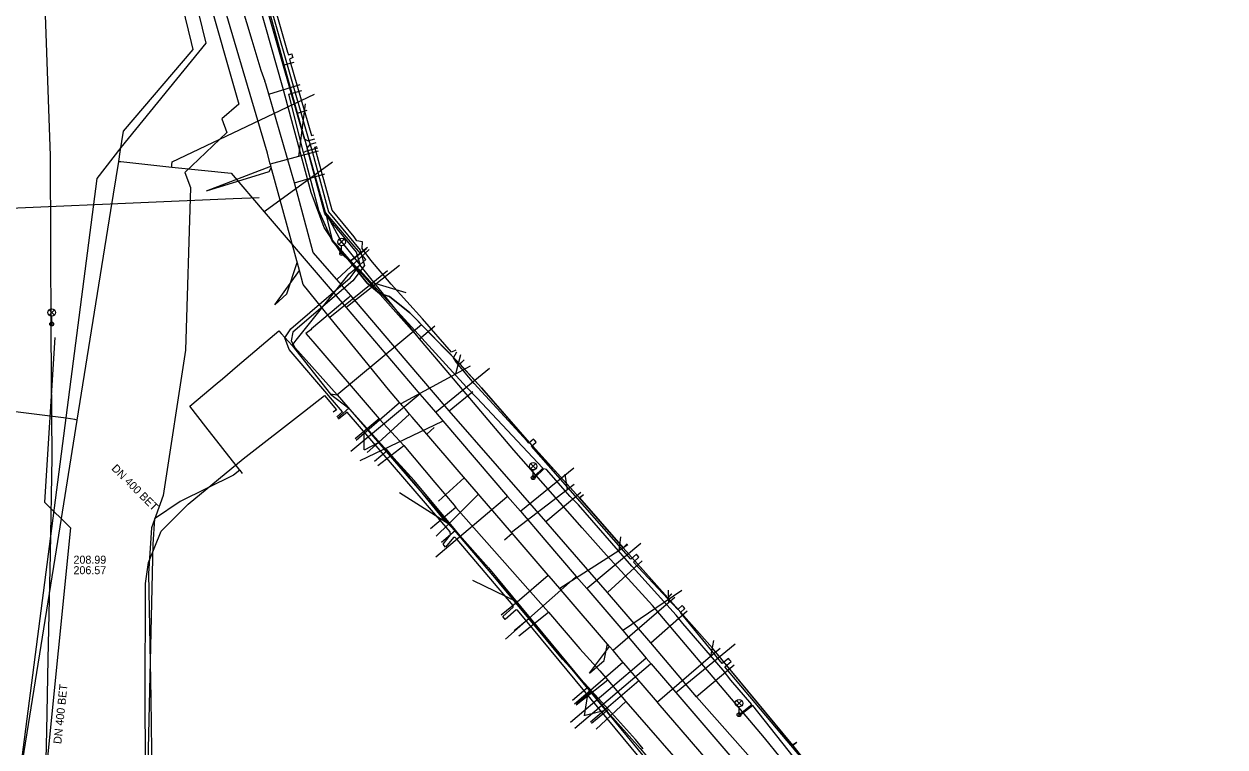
# Model space of a CAD drawing. Extents: x -596228 to -595156, y -1161235 to -1159373.
# Drawn here: x -595381.6 to -595261.6, y -1160803.8 to -1160731.5 of the extents above; entities that cross this region are included whole.
import ezdxf

# ---------------------------------------------------------------- set-up
doc = ezdxf.new("R2010")
doc.units = 0
for name, color, linetype in [('Vrstva 1', 7, 'Continuous'), ('Vrstva 12', 7, 'Continuous'), ('Vrstva 14', 7, 'Continuous'), ('Vrstva 16', 7, 'Continuous'), ('Vrstva 19', 7, 'Continuous'), ('Vrstva 33', 7, 'Continuous'), ('Vrstva 4', 7, 'Continuous'), ('Vrstva 42', 7, 'Continuous'), ('Vrstva 55', 7, 'Continuous'), ('Vrstva 58', 7, 'Continuous'), ('Vrstva 9', 7, 'Continuous')]:
    doc.layers.add(name, color=color, linetype=linetype)

msp = doc.modelspace()

# ---------------------------------------------------------------- linework, layer by layer
at = {"layer": 'Vrstva 1'}
for p, q in [((-595353.54, -1160739.478), (-595354.196, -1160744.737)), ((-595363.38, -1160748.17), (-595356.952, -1160745.709)), ((-595356.55, -1160759.55), (-595354.099, -1160756.146)), ((-595343.414, -1160758.352), (-595346.772, -1160757.366)), ((-595378.54, -1160762.82), (-595379.58, -1160779.28)), ((-595338.006, -1160764.578), (-595338.509, -1160766.51)), ((-595340.631, -1160771.837), (-595341.374, -1160772.48)), ((-595347.635, -1160774.049), (-595347.643, -1160772.399)), ((-595347.59, -1160774.05), (-595346.195, -1160773.314)), ((-595340.184, -1160779.176), (-595337.634, -1160776.852)), ((-595327.564, -1160776.487), (-595327.344, -1160778.072)), ((-595379.58, -1160779.28), (-595376.97, -1160781.85)), ((-595344.09, -1160778.322), (-595339.178, -1160781.454)), ((-595376.97, -1160781.85), (-595379.56, -1160807.66)), ((-595333.602, -1160783.048), (-595332.844, -1160782.396)), ((-595321.998, -1160782.743), (-595322.188, -1160784.155)), ((-595336.8, -1160787.086), (-595332.345, -1160789.262)), ((-595317.258, -1160788.075), (-595317.214, -1160789.37)), ((-595325.1, -1160796.38), (-595323.107, -1160793.714)), ((-595312.705, -1160793.132), (-595313, -1160794.729)), ((-595325.604, -1160800.653), (-595325.25, -1160798.276)), ((-595325.527, -1160800.591), (-595323.666, -1160800.118))]:
    msp.add_line(p, q, dxfattribs=at)
for points in [[(-595363.383, -1160748.172), (-595357.116, -1160746.23), (-595356.909, -1160745.863)], [(-595356.546, -1160759.549), (-595355.349, -1160758.459), (-595354.326, -1160755.316)], [(-595325.103, -1160796.376), (-595323.652, -1160795.129), (-595323.323, -1160793.464)]]:
    msp.add_lwpolyline(points, dxfattribs=at)
at = {"layer": 'Vrstva 12'}
for p, q in [((-595355.61, -1160735.58), (-595357.25, -1160729.61)), ((-595355.61, -1160735.58), (-595354.64, -1160735.32)), ((-595354.28, -1160740.39), (-595355.61, -1160735.58)), ((-595354.28, -1160740.39), (-595353.32, -1160740.12)), ((-595351.5, -1160750.34), (-595354.28, -1160740.39)), ((-595351.5, -1160750.34), (-595349.93, -1160753.24)), ((-595351.5, -1160750.34), (-595350.84, -1160753.1)), ((-595350.84, -1160753.1), (-595348.4, -1160755.86)), ((-595349.93, -1160753.24), (-595348.06, -1160755.57)), ((-595347.3, -1160753.84), (-595349.05, -1160755.22)), ((-595348.4, -1160755.86), (-595348.06, -1160755.57)), ((-595348.4, -1160755.86), (-595342.09, -1160762.98)), ((-595342.09, -1160762.98), (-595348.06, -1160755.57)), ((-595342.21, -1160761.24), (-595341.9, -1160761.56)), ((-595355.94, -1160762.42), (-595354.84, -1160763.62)), ((-595342.09, -1160762.98), (-595340.58, -1160761.66)), ((-595341.9, -1160761.56), (-595338.07, -1160765.48)), ((-595354.84, -1160763.62), (-595350.98, -1160768.5)), ((-595337.62, -1160765.05), (-595338.07, -1160765.48)), ((-595361.8, -1160766.95), (-595360.28, -1160765.65)), ((-595362.33, -1160767.41), (-595361.8, -1160766.95)), ((-595350.98, -1160768.5), (-595349.15, -1160769.91)), ((-595349.15, -1160769.91), (-595350.29, -1160770.89)), ((-595345.33, -1160774.15), (-595349.15, -1160769.91)), ((-595360.07, -1160776.1), (-595363.45, -1160771.76)), ((-595345.33, -1160774.15), (-595346.6, -1160775.22)), ((-595360.07, -1160776.1), (-595359.82, -1160776.41)), ((-595327.7, -1160777.09), (-595326.11, -1160778.86)), ((-595325.71, -1160778.57), (-595326.11, -1160778.86)), ((-595326.11, -1160778.86), (-595321.74, -1160783.87)), ((-595339.91, -1160783.28), (-595338.51, -1160782.1)), ((-595331.18, -1160790.91), (-595338.51, -1160782.1)), ((-595321.35, -1160783.45), (-595321.74, -1160783.87)), ((-595321.74, -1160783.87), (-595319.74, -1160786.1)), ((-595332.62, -1160792.13), (-595331.18, -1160790.91)), ((-595325.23, -1160797.8), (-595326.82, -1160799.11)), ((-595323.21, -1160800.02), (-595325.23, -1160797.8)), ((-595323.21, -1160800.02), (-595324.91, -1160801.41)), ((-595320.5, -1160803.01), (-595323.21, -1160800.02)), ((-595319.73, -1160803.94), (-595320.5, -1160803.01)), ((-595306.05, -1160804.79), (-595307.62, -1160802.85)), ((-595304.41, -1160803.31), (-595304.8, -1160803.59)), ((-595304.8, -1160803.59), (-595302.74, -1160806.18))]:
    msp.add_line(p, q, dxfattribs=at)
for points in [[(-595353.68, -1160744.35), (-595355.17, -1160738.52), (-595353.86, -1160738.15)], [(-595353.68, -1160744.35), (-595353.46, -1160744.19), (-595352.27, -1160743.86)], [(-595349.05, -1160755.22), (-595350.82, -1160753.15), (-595352.17, -1160750.14), (-595353.68, -1160744.35)], [(-595348.06, -1160755.57), (-595347.45, -1160755.04), (-595348.62, -1160753.69), (-595351.5, -1160750.34)], [(-595349.05, -1160755.22), (-595347.34, -1160757.39), (-595346.11, -1160758.42), (-595345.11, -1160758.74), (-595343.08, -1160760.36), (-595342.21, -1160761.24)], [(-595354.84, -1160763.62), (-595354.43, -1160763.11), (-595349.12, -1160756.48), (-595348.4, -1160755.86)], [(-595360.28, -1160765.65), (-595356.17, -1160762.15), (-595355.94, -1160762.42)], [(-595341.9, -1160761.56), (-595350.35, -1160768.6), (-595350.98, -1160768.5)], [(-595325.83, -1160781.85), (-595332.67, -1160774.09), (-595337.43, -1160768.47), (-595339.44, -1160766.1), (-595342.09, -1160762.98)], [(-595338.07, -1160765.48), (-595335.91, -1160767.87), (-595331.12, -1160773.34), (-595327.7, -1160777.09)], [(-595363.45, -1160771.76), (-595365.05, -1160769.71), (-595362.33, -1160767.41)], [(-595338.51, -1160782.1), (-595342.64, -1160777.12), (-595345.33, -1160774.15)], [(-595360.07, -1160776.1), (-595360.7, -1160776.59), (-595366.01, -1160779.21), (-595368.58, -1160780.95), (-595368.76, -1160783.5), (-595369.34, -1160809.83), (-595368.87, -1160823.11), (-595369.36, -1160828.18), (-595370.51, -1160846.06), (-595370.42, -1160863.54), (-595369.37, -1160876.51), (-595370.12, -1160885.48)], [(-595307.62, -1160802.85), (-595318.81, -1160789.62), (-595323.72, -1160784.25), (-595325.83, -1160781.85)], [(-595319.74, -1160786.1), (-595317.27, -1160788.86), (-595316.89, -1160788.46)], [(-595304.8, -1160803.59), (-595312.81, -1160793.88), (-595317.27, -1160788.86)], [(-595325.23, -1160797.8), (-595327.79, -1160794.98), (-595331.18, -1160790.91)]]:
    msp.add_lwpolyline(points, dxfattribs=at)
at = {"layer": 'Vrstva 14'}
for p, q in [((-595372.161, -1160745.224), (-595372.009, -1160744.278)), ((-595372.949, -1160750.146), (-595372.161, -1160745.224)), ((-595372.161, -1160745.224), (-595371.95, -1160745.249))]:
    msp.add_line(p, q, dxfattribs=at)
for points in [[(-595392.386, -1160880.463), (-595389, -1160860.26), (-595382.285, -1160808.426), (-595374.317, -1160746.92), (-595371.904, -1160743.843), (-595363.417, -1160733.399), (-595367.988, -1160714.713), (-595370.468, -1160704.744)], [(-595372.009, -1160744.278), (-595371.677, -1160742.203), (-595364.729, -1160734.03), (-595364.893, -1160733.351), (-595369.315, -1160715.062)], [(-595366.865, -1160745.817), (-595366.84, -1160745.56), (-595366.811, -1160745.281), (-595352.604, -1160738.508)], [(-595371.95, -1160745.249), (-595366.865, -1160745.817), (-595360.935, -1160746.418), (-595357.631, -1160750.253), (-595353.009, -1160755.617), (-595349.428, -1160759.829), (-595342.068, -1160768.489), (-595341.378, -1160769.3), (-595340.511, -1160770.31), (-595339.773, -1160771.169), (-595333.287, -1160778.721), (-595332.011, -1160780.207), (-595329.559, -1160783.063), (-595326.425, -1160786.719), (-595325.383, -1160787.935), (-595321.785, -1160792.133), (-595319.43, -1160794.881), (-595318.95, -1160795.441), (-595317.724, -1160796.871), (-595316.471, -1160798.334), (-595310.689, -1160805.087)], [(-595357.631, -1160750.253), (-595357.527, -1160750.175), (-595350.786, -1160745.27)], [(-595393.342, -1160876.76), (-595392.99, -1160875.24), (-595390.499, -1160859.689), (-595390.026, -1160856.737), (-595387.754, -1160842.558), (-595386.046, -1160831.895), (-595382.445, -1160809.421), (-595378.386, -1160784.054), (-595376.306, -1160771.081), (-595374.576, -1160760.301), (-595372.949, -1160750.146)], [(-595349.428, -1160759.829), (-595349.286, -1160759.711), (-595344.08, -1160755.607)], [(-595340.511, -1160770.31), (-595340.402, -1160770.217), (-595335.108, -1160765.885)], [(-595376.306, -1160771.081), (-595376.552, -1160771.04), (-595377.425, -1160770.909), (-595399.638, -1160768.145), (-595428.371, -1160773.614)], [(-595342.068, -1160768.489), (-595342.242, -1160768.634), (-595348.969, -1160774.24)], [(-595339.773, -1160771.169), (-595339.825, -1160771.216), (-595348.046, -1160775.158)], [(-595332.011, -1160780.207), (-595331.957, -1160780.162), (-595326.671, -1160775.86)], [(-595333.287, -1160778.721), (-595333.37, -1160778.792), (-595340.467, -1160784.801)], [(-595325.383, -1160787.935), (-595325.262, -1160787.834), (-595319.975, -1160783.387)], [(-595326.425, -1160786.719), (-595326.504, -1160786.784), (-595333.507, -1160792.987)], [(-595321.785, -1160792.133), (-595321.702, -1160792.066), (-595315.891, -1160788.092)], [(-595316.471, -1160798.334), (-595316.3, -1160798.195), (-595310.541, -1160793.446)], [(-595319.43, -1160794.881), (-595319.464, -1160794.909), (-595327.011, -1160801.317)], [(-595318.95, -1160795.441), (-595319.02, -1160795.501), (-595326.568, -1160801.907)]]:
    msp.add_lwpolyline(points, dxfattribs=at)
at = {"layer": 'Vrstva 16'}
msp.add_lwpolyline([(-595391.495, -1160750.254), (-595360.707, -1160748.948), (-595358.13, -1160748.839)], dxfattribs=at)
at = {"layer": 'Vrstva 19'}
for p, q in [((-595357.15, -1160738.49), (-595354.03, -1160737.54)), ((-595354.58, -1160747.36), (-595351.55, -1160746.47)), ((-595350.37, -1160757.03), (-595347.14, -1160754.03)), ((-595339.14, -1160770.17), (-595336.774, -1160768.238)), ((-595346.13, -1160770.95), (-595348.54, -1160772.95)), ((-595346.27, -1160775.61), (-595343.65, -1160773.64)), ((-595329.47, -1160781.23), (-595325.96, -1160778.29)), ((-595338.46, -1160779.84), (-595340.99, -1160781.97)), ((-595323.32, -1160788.31), (-595319.83, -1160785.16)), ((-595318.99, -1160793.35), (-595315.33, -1160790.17)), ((-595332.17, -1160792.67), (-595329.21, -1160790.29)), ((-595310.65, -1160795.6), (-595314.42, -1160798.75)), ((-595323.29, -1160797.08), (-595326.43, -1160799.57)), ((-595324.45, -1160801.97), (-595321.46, -1160799.23))]:
    msp.add_line(p, q, dxfattribs=at)
for points in [[(-595362.481, -1160721.052), (-595358.862, -1160733.1), (-595357.941, -1160736.107), (-595357.542, -1160737.214)], [(-595261.59, -1160858.75), (-595265.46, -1160854.47), (-595266.98, -1160852.77), (-595267.11, -1160852.64), (-595271.14, -1160847.87), (-595278.76, -1160839.33), (-595285.31, -1160831.9), (-595289.42, -1160827.31), (-595293.96, -1160822.16), (-595300.15, -1160815), (-595305.41, -1160808.92), (-595314.42, -1160798.75), (-595318.99, -1160793.35), (-595323.32, -1160788.31), (-595329.47, -1160781.23), (-595339.14, -1160770.17), (-595343.434, -1160765.124), (-595348.96, -1160758.63), (-595350.37, -1160757.03), (-595352.73, -1160754.32), (-595354.58, -1160747.36), (-595357.15, -1160738.49), (-595357.46, -1160737.46), (-595357.542, -1160737.214)], [(-595348.96, -1160758.63), (-595349.15, -1160758.84), (-595352.89, -1160761.97), (-595352.97, -1160762.05), (-595353.45, -1160762.44), (-595352.76, -1160763.24), (-595346.13, -1160770.95), (-595343.65, -1160773.64), (-595340.56, -1160777.31), (-595338.64, -1160779.59), (-595338.46, -1160779.84), (-595329.21, -1160790.29), (-595326.06, -1160793.95), (-595324.07, -1160796.14), (-595323.29, -1160797.08), (-595321.46, -1160799.23), (-595314.46, -1160807.27)]]:
    msp.add_lwpolyline(points, dxfattribs=at)
at = {"layer": 'Vrstva 33'}
for p, q in [((-595350.148, -1160753.015), (-595349.618, -1160753.545)), ((-595350.148, -1160753.545), (-595349.618, -1160753.015)), ((-595349.883, -1160754.43), (-595349.883, -1160753.655)), ((-595379.12, -1160760.07), (-595378.59, -1160760.6)), ((-595379.12, -1160760.6), (-595378.59, -1160760.07)), ((-595378.855, -1160761.485), (-595378.855, -1160760.71)), ((-595331.005, -1160775.435), (-595330.475, -1160775.965)), ((-595331.005, -1160775.965), (-595330.475, -1160775.435)), ((-595330.74, -1160776.85), (-595330.74, -1160776.075)), ((-595310.425, -1160799.125), (-595309.895, -1160799.655)), ((-595310.425, -1160799.655), (-595309.895, -1160799.125)), ((-595310.16, -1160800.54), (-595310.16, -1160799.765))]:
    msp.add_line(p, q, dxfattribs=at)
for centre, radius in [((-595349.883, -1160753.28), 0.375), ((-595349.883, -1160754.43), 0.19), ((-595349.883, -1160754.43), 0.05), ((-595378.855, -1160760.335), 0.375), ((-595378.855, -1160761.485), 0.19), ((-595378.855, -1160761.485), 0.05), ((-595330.74, -1160775.7), 0.375), ((-595330.74, -1160776.85), 0.19), ((-595330.74, -1160776.85), 0.05), ((-595310.16, -1160799.39), 0.375), ((-595310.16, -1160800.54), 0.19), ((-595310.16, -1160800.54), 0.05)]:
    msp.add_circle(centre, radius, dxfattribs=at)
at = {"layer": 'Vrstva 42'}
for points in [[(-595380.27, -1160633.24), (-595377.4, -1160645.18), (-595375.67, -1160653.1), (-595374.22, -1160655.15), (-595374.79, -1160657.51), (-595372.35, -1160670.73), (-595370.65, -1160682.01), (-595368.17, -1160693.47), (-595369.28, -1160698.11), (-595367.68, -1160714.03), (-595363.44, -1160727.92), (-595360.16, -1160739.49), (-595361.87, -1160740.96), (-595361.36, -1160742.32), (-595365.54, -1160746.32), (-595364.99, -1160747.83), (-595365.5, -1160764.11), (-595367.73, -1160778.64), (-595368.89, -1160781.86), (-595369.17, -1160786.42), (-595368.95, -1160798.91), (-595368.74, -1160814.52)], [(-595396.614, -1160713.132), (-595396.204, -1160713.683), (-595395.665, -1160713.838), (-595394.409, -1160713.594), (-595393.933, -1160713.329), (-595391.712, -1160712.135), (-595379.084, -1160708.412), (-595368.822, -1160705.4), (-595364.445, -1160704.517), (-595363.715, -1160704.331), (-595363.086, -1160704.43), (-595362.886, -1160704.462), (-595362.379, -1160704.61), (-595362.226, -1160704.998), (-595361.784, -1160713.929), (-595361.367, -1160715.919), (-595355.789, -1160735.449), (-595353.616, -1160742.962), (-595353.235, -1160743.16), (-595353.148, -1160743.136), (-595352.549, -1160742.969)], [(-595360.978, -1160715.823), (-595355.405, -1160735.338), (-595353.148, -1160743.136), (-595353.029, -1160743.549), (-595352.804, -1160744.325), (-595351.199, -1160750.278), (-595348.032, -1160754.113), (-595347.58, -1160755.623), (-595348.773, -1160757.17), (-595354.755, -1160762.307), (-595354.937, -1160763.179), (-595354.564, -1160763.832), (-595350.311, -1160768.571), (-595338.222, -1160782.556), (-595332.49, -1160789.297), (-595331.951, -1160789.894), (-595316.434, -1160808.636)], [(-595360.589, -1160715.727), (-595355.296, -1160734.291), (-595355.204, -1160734.577), (-595354.867, -1160734.469), (-595354.821, -1160734.656), (-595354.769, -1160734.841), (-595355.09, -1160735.001), (-595355.01, -1160735.281), (-595352.887, -1160742.647), (-595352.657, -1160742.582)], [(-595350.351, -1160770.757), (-595349.794, -1160770.273), (-595355.118, -1160764.042), (-595355.572, -1160762.868), (-595354.961, -1160761.952), (-595349.025, -1160756.851), (-595348.022, -1160755.541), (-595348.392, -1160754.305), (-595351.563, -1160750.466), (-595353.341, -1160743.901), (-595353.029, -1160743.549), (-595352.991, -1160743.506), (-595352.442, -1160743.352)], [(-595347.81, -1160753.27), (-595348.37, -1160753.15), (-595348.618, -1160752.775), (-595350.835, -1160750.09), (-595352.546, -1160743.797), (-595352.334, -1160743.738)], [(-595338.464, -1160764.084), (-595338.9, -1160764.3), (-595341.8, -1160760.95), (-595344.93, -1160757.49), (-595346.97, -1160755.11), (-595347.84, -1160753.92), (-595347.81, -1160753.27)], [(-595294.118, -1160816.475), (-595311.577, -1160795.738), (-595310.951, -1160795.232), (-595311.077, -1160795.077), (-595311.202, -1160794.921), (-595311.832, -1160795.431), (-595316.021, -1160790.311), (-595315.575, -1160789.906), (-595315.709, -1160789.758), (-595315.844, -1160789.61), (-595316.287, -1160790.012), (-595320.723, -1160785.291), (-595320.159, -1160784.789), (-595320.292, -1160784.64), (-595320.425, -1160784.49), (-595320.989, -1160784.992), (-595330.891, -1160773.701), (-595330.43, -1160773.289), (-595330.563, -1160773.14), (-595330.697, -1160772.991), (-595331.155, -1160773.4), (-595331.33, -1160773.2), (-595336.63, -1160767.42), (-595338.39, -1160765.34), (-595338.69, -1160764.87), (-595338.353, -1160764.254)], [(-595353.602, -1160770.201), (-595351.587, -1160768.633), (-595350.403, -1160770.053), (-595350.742, -1160770.31)], [(-595360.942, -1160887.953), (-595361.681, -1160887.771), (-595361.89, -1160887.789), (-595368.555, -1160888.332), (-595369.891, -1160880.348), (-595369.758, -1160837.889), (-595369.417, -1160815.417), (-595369.511, -1160799.294), (-595369.472, -1160787.438), (-595369.168, -1160785.319), (-595367.921, -1160782.202), (-595365.224, -1160779.48), (-595359.713, -1160774.957), (-595353.602, -1160770.201)], [(-595316.793, -1160808.855), (-595332.302, -1160790.089), (-595332.434, -1160790.043), (-595333.528, -1160791.034), (-595333.649, -1160790.883), (-595333.775, -1160790.731), (-595332.737, -1160789.797), (-595332.749, -1160789.619), (-595338.341, -1160783.037), (-595338.526, -1160782.816), (-595338.708, -1160782.83), (-595339.493, -1160783.793), (-595339.621, -1160783.639), (-595339.745, -1160783.484), (-595338.983, -1160782.549), (-595339.019, -1160782.243), (-595349.339, -1160770.3), (-595350.183, -1160771.009)]]:
    msp.add_lwpolyline(points, dxfattribs=at)
at = {"layer": 'Vrstva 55'}
for points in [[(-595382.63, -1160688.57), (-595379.98, -1160718.41), (-595379.59, -1160728.68), (-595379.02, -1160744.68), (-595378.93, -1160762.25), (-595378.85, -1160774.77), (-595379.02, -1160784.49), (-595379.24, -1160794.98), (-595379.39, -1160802.14), (-595379.54, -1160809.29)], [(-595303.47, -1160806.31), (-595308.793, -1160799.617), (-595309.951, -1160800.534), (-595310.081, -1160800.577), (-595310.16, -1160800.54), (-595310.119, -1160800.463), (-595310.009, -1160800.426), (-595308.869, -1160799.524), (-595310.97, -1160797.07), (-595311.75, -1160796.1), (-595315.79, -1160791.42), (-595316.44, -1160790.6), (-595320.16, -1160786.45), (-595320.89, -1160785.68), (-595326.19, -1160779.57), (-595327.03, -1160778.71), (-595329.42, -1160776.04), (-595329.663, -1160775.969), (-595330.523, -1160776.788), (-595330.656, -1160776.869), (-595330.74, -1160776.85), (-595330.719, -1160776.767), (-595330.597, -1160776.692), (-595329.771, -1160775.906), (-595336.358, -1160768.868), (-595337.395, -1160767.784), (-595348.07, -1160756.09), (-595349.19, -1160755.09), (-595349.805, -1160754.522), (-595349.883, -1160754.43), (-595351.61, -1160751.84), (-595352.94, -1160748.34), (-595355.76, -1160737.85), (-595358.664, -1160727.558)]]:
    msp.add_lwpolyline(points, dxfattribs=at)
at = {"layer": 'Vrstva 58'}
for p, q in [((-595349.053, -1160755.218), (-595347.395, -1160753.919)), ((-595338.074, -1160765.476), (-595343.077, -1160760.357)), ((-595338.074, -1160765.476), (-595337.671, -1160765.087)), ((-595335.91, -1160767.874), (-595338.074, -1160765.476)), ((-595326.113, -1160778.856), (-595325.726, -1160778.57)), ((-595321.744, -1160783.867), (-595321.351, -1160783.453)), ((-595317.268, -1160788.864), (-595316.899, -1160788.472)), ((-595326.435, -1160799.39), (-595324.963, -1160798.23)), ((-595304.799, -1160803.593), (-595304.377, -1160803.293))]:
    msp.add_line(p, q, dxfattribs=at)
for points in [[(-595353.679, -1160744.345), (-595353.458, -1160744.19), (-595352.328, -1160743.876)], [(-595343.077, -1160760.357), (-595345.105, -1160758.738), (-595346.105, -1160758.415), (-595347.342, -1160757.394), (-595349.053, -1160755.218), (-595350.819, -1160753.147), (-595352.167, -1160750.138), (-595353.679, -1160744.345)], [(-595288.613, -1160822.488), (-595292.598, -1160817.872), (-595293.595, -1160816.771), (-595302.742, -1160806.177), (-595304.799, -1160803.593), (-595312.811, -1160793.877), (-595317.268, -1160788.864), (-595321.744, -1160783.867), (-595326.113, -1160778.856), (-595331.116, -1160773.337), (-595335.91, -1160767.874)], [(-595345.436, -1160773.982), (-595339.785, -1160780.875), (-595338.09, -1160782.606), (-595335.186, -1160785.87), (-595324.963, -1160798.23)], [(-595324.963, -1160798.23), (-595323.338, -1160800.218), (-595320.038, -1160803.903), (-595314.928, -1160809.919)]]:
    msp.add_lwpolyline(points, dxfattribs=at)
at = {"layer": 'Vrstva 9'}
msp.add_line((-595357.305, -1160744.416), (-595366.69, -1160712.38), dxfattribs=at)
for points in [[(-595353.719, -1160757.535), (-595354.099, -1160756.146), (-595356.952, -1160745.709), (-595356.973, -1160745.632), (-595357.007, -1160745.506), (-595357.305, -1160744.416)], [(-595352.229, -1160744.199), (-595354.196, -1160744.737), (-595357.007, -1160745.506)], [(-595345.302, -1160756.173), (-595346.772, -1160757.366), (-595351.043, -1160760.831)], [(-595345.197, -1160768.038), (-595347.531, -1160765.16), (-595351.043, -1160760.831), (-595353.719, -1160757.535)], [(-595337.022, -1160765.71), (-595338.509, -1160766.51), (-595343.976, -1160769.456)], [(-595315.112, -1160803.009), (-595318.229, -1160799.385), (-595318.307, -1160799.294), (-595319.937, -1160797.399), (-595320.179, -1160797.118), (-595321.672, -1160795.382), (-595321.763, -1160795.276), (-595322.552, -1160794.359), (-595322.748, -1160794.131), (-595323.107, -1160793.714), (-595327.939, -1160788.097), (-595328.083, -1160787.93), (-595329.139, -1160786.702), (-595329.237, -1160786.588), (-595332.844, -1160782.396), (-595332.902, -1160782.328), (-595336.026, -1160778.697), (-595336.215, -1160778.477), (-595338.126, -1160776.256), (-595341.374, -1160772.48), (-595342.822, -1160770.798), (-595343.089, -1160770.487), (-595343.513, -1160769.994), (-595343.8, -1160769.661), (-595343.976, -1160769.456), (-595344.08, -1160769.334), (-595345.197, -1160768.038)], [(-595348.441, -1160773.086), (-595347.643, -1160772.399), (-595344.08, -1160769.334)], [(-595347.316, -1160774.335), (-595346.195, -1160773.314), (-595343.089, -1160770.487)], [(-595326.637, -1160777.53), (-595327.344, -1160778.072), (-595332.902, -1160782.328)], [(-595340.445, -1160782.704), (-595339.178, -1160781.454), (-595336.215, -1160778.477)], [(-595321.267, -1160783.565), (-595322.188, -1160784.155), (-595328.083, -1160787.93)], [(-595333.92, -1160790.567), (-595332.345, -1160789.262), (-595329.237, -1160786.588)], [(-595316.582, -1160788.826), (-595317.214, -1160789.37), (-595322.748, -1160794.131)], [(-595312.06, -1160793.92), (-595313, -1160794.729), (-595318.307, -1160799.294)], [(-595326.614, -1160799.449), (-595325.25, -1160798.276), (-595321.763, -1160795.276)], [(-595324.99, -1160801.257), (-595323.666, -1160800.118), (-595320.179, -1160797.118)], [(-595312.844, -1160805.652), (-595315.112, -1160803.009)]]:
    msp.add_lwpolyline(points, dxfattribs=at)

# ---------------------------------------------------------------- texts
at = {"layer": 'Vrstva 4'}
for rotation, p in [(315, (-595372.941, -1160775.988)), (84, (-595377.903, -1160803.496))]:
    msp.add_text('DN 400 BET', height=0.8, rotation=rotation, dxfattribs=at).set_placement(p)
for s, p in [('208.99', (-595376.681, -1160785.444)), ('206.57', (-595376.681, -1160786.494))]:
    msp.add_text(s, height=0.8, dxfattribs=at).set_placement(p)

doc.saveas('drawing.dxf')
